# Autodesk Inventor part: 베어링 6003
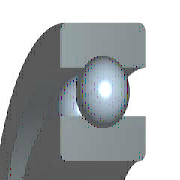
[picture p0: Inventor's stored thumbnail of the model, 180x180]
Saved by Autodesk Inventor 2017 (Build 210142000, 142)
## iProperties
Created: 2012-02
Part Number: 베어링 6003
Material: 강철, 연강
Description: 깊은 그루브 볼 베어링
Document SubType Name: Modeling
Standard: KS B 2023
Designer: mduedu
Standards Organization: KS
Language: ko-KR
Size Designation: 6003 - 17 x 35 x 10
Categories: <MemberInstance><Categories><Category DisplayName="샤프트 부품" InternalName="7f7aeb1f-a693-4053-b835-cee3144e0d98" Mnemonic="SHFT"><Category DisplayName="베어링" Inter
Density: 1 g/cm^3
Appearance: 노란색
IsCustomPart: 1
Author: mduedu
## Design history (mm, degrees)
sketch "스케치" dims "d0" = 4.68 (= -0.26 x WD + 0.26 x BD)
  geometry: L1 (2.66, 13)-(7.34, 13); L2 (5, 13)-(5, 10.66); L3 (5, 13)-(5, 15.34); L4 (3.261, 11.434)-(0, 11.434); L5 (0, 8.5)-(10, 8.5); L6 (3.261, 14.566)-(0, 14.566); L7 (0, 17.5)-(10, 17.5); L8 (10, 8.5)-(10, 11.434); L9 (6.739, 11.434)-(10, 11.434); L10 (6.739, 14.566)-(10, 14.566); L11 (10, 17.5)-(10, 14.566); L12 (-1.4, 0)-(8.4, 0) reference; L13 (0, -0.3)-(0, 5.3) reference
  constraints: 22 end point, 4 point on line, 2 collinear, 2 perpendicular, 2 symmetric about line, 1 midpoint, 1 parallel, 14 other
  dimensions: "d9" = 17 diameter of L5 L12 (= WD); "d11" = 35 diameter of L7 L12 (= BD); "d12" = 10 distance between parallel lines of L8 L13 (= KB); "d13" = 22.868 diameter of L9 L12 (= 0.326 x BD + 0.674 x WD)
revolve "본체" stored, may be unused: angle "d6" = 90 deg
revolve "볼" stored, may be unused: angle "d7" = 90 deg
pattern_circular "IDS_ARRAYBALL[SIMPL:T]" dims angle "d3" = 360 deg
body "Solid1"
fillet "모깎기1" dims "d1" = 0.3 (= KRS)
other parameters: "WD" = 17 [user parameter; used in 5 equation terms], "BD" = 35 [user parameter; used in 5 equation terms], "KB" = 10 [user parameter; used in 1 equation term], "KRS" = 0.3 [user parameter; used in 1 equation term], "d4" = 0, "d5" = 0, "d8" = 0, "d14" = 0, "d15" = 0, "BBA" = 0 [user parameter], "BC0" = 3250000 [user parameter], "BC" = 6050000 [user parameter], "BR" = 17.5 (= 0.5 x BD) [user parameter], "WR" = 8.5 (= 0.5 x WD) [user parameter]
